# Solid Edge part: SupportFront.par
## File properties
Author: wojci
Template: ISO Metric Part.par
Last saved by: wojci
Revision: 29
Application: Solid Edge
Username: wojci
Accuracy: 0.990
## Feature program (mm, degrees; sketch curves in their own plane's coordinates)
sketch for "unnamed Protrusion 1" plane through (0, 0, 0) normal (0, -1, 0) x-axis (1, 0, 0)
  line (8, 17) -> (29.5448, 47.6494)
  line (3, 0) -> (8, 17)
  line (0, 0) -> (3, 0)
  line (0, 0) -> (0, 54.25)
  line (0, 54.25) -> (3, 54.25)
  line (3, 54.25) -> (15.254, 54.25)
extrude "unnamed Protrusion 1" add finite 20 along -normal
fillet "Round_2" radius 20
sketch for "ExtrudedCutout_8" plane through (14, 20, 28.625) normal (0, 1, 0) x-axis (-1, 0, 0)
extrude "ExtrudedCutout_8" cut finite 10 along -normal
sketch for "unnamed Cutout 1" plane through (9.0718, 10, 57.6326) normal (0, 0, 1) x-axis (-1, 0, 0)
  line (-21.9282, -10) -> (5.0718, -10)
extrude "unnamed Cutout 1" cut through along -normal
sketch for "Hole_1" plane through (13.5, 0, 28.5) normal (0, -1, 0) x-axis (0.575078, 0, 0.818099)
  hole centre (24.8931, 5.8862) bore radius 1.5
hole "Hole_1" diameter 3 finite
sketch for "ExtrudedProtrusion_2" #1 plane through (0, 5, 27) normal (-1, 0, 0) x-axis (0, 0, -1)
  line (-27.25, -7.25) -> (-17.5, -7.25)
  line (-17.5, -7.25) -> (-17.5, -12.75)
  line (-17.5, -12.75) -> (-27.25, -12.75)
  line (-27.25, -12.75) -> (-27.25, -7.25)
sketch for "ExtrudedProtrusion_2" #2 plane through (0, 5, 27) normal (-1, 0, 0) x-axis (0, 0, -1)
  line (10.25, -7.25) -> (10.25, -12.75)
  line (10.25, -12.75) -> (24.75, -12.75)
  line (24.75, -12.75) -> (24.75, -7.25)
  line (24.75, -7.25) -> (10.25, -7.25)
extrude "ExtrudedProtrusion_2" add finite 1.25 along +normal
sketch for "Hole_2" plane through (-1.25, 5, 49.125) normal (-1, 0, 0) x-axis (0, -1, 0)
  hole centre (-10, 0.125) bore radius 1.2295
hole "Hole_2" nominal diameter 3 through  ThreadDepth = 6.2 mm
sketch for "unnamed Hole 1" plane through (-1.25, 5, 49.125) normal (-1, 0, 0) x-axis (0, -1, 0)
  hole centre (-10, -36.125) bore radius 1.2295
hole "unnamed Hole 1" through
sketch for "unnamed Hole 2" plane through (-1.25, 5, 49.125) normal (-1, 0, 0) x-axis (0, -1, 0)
  hole centre (-10, -43.125) bore radius 1.2295
hole "unnamed Hole 2" through
pattern "unnamed Pattern 1" of "Hole_2", "unnamed Hole 1", "unnamed Hole 2"
sketch for "unnamed Cutout 2" #1 plane through (2.75, 5, 49.125) normal (-1, 0, 0) x-axis (0, -1, 0)
  circle centre (-10, -36.125) radius 3.25
sketch for "unnamed Cutout 2" #2 plane through (2.75, 5, 49.125) normal (-1, 0, 0) x-axis (0, -1, 0)
  circle centre (-10, -43.125) radius 3.25
extrude "unnamed Cutout 2" cut through along -normal
sketch for "unnamed Cutout 3" plane through (2.75, 5, 49.125) normal (-1, 0, 0) x-axis (0, -1, 0)
  circle centre (-10, 0.125) radius 3.25
extrude "unnamed Cutout 3" cut through along -normal
sketch for "unnamed Cutout 4" plane through (0, 10, 54.25) normal (-0.965107, -0.2586, 0.04117) x-axis (0, -0.157224, -0.987563)
  line (1.5722, 10.2327) -> (0, 0)
  line (0, 0) -> (50.8828, 0)
  line (50.8828, 0) -> (51.199, 2.058)
  line (51.199, 2.058) -> (1.5722, 10.2327)
extrude "unnamed Cutout 4" cut through along +normal
sketch for "unnamed Cutout 5" plane through (1.5, 10, 0) normal (0, 0, -1) x-axis (0, -1, 0)
  line (10, 1.5) -> (8, 1.5)
  line (8, 1.5) -> (10, 0.9641)
  line (10, 0.9641) -> (10, 1.5)
extrude "unnamed Cutout 5" cut through along -normal
sketch for "ExtrudedCutout_13" plane through (14.2679, 0, 28.625) normal (0, -1, 0) x-axis (1, 0, 0)
  line (-14.345, -27.625) -> (-10.2843, -25.2805)
  line (-11.2679, -28.625) -> (-10.2843, -25.2805)
  line (-11.2679, -28.625) -> (-15.5179, -28.625)
  line (-15.5179, -28.625) -> (-15.5179, -27.625)
  line (-15.5179, -27.625) -> (-14.345, -27.625)
extrude "ExtrudedCutout_13" cut finite 10 along -normal
sketch used by "unnamed Cutout 6" plane through (15.5, 10, 43.2085) normal (0, 1, 0) x-axis (-1, 0, 0)
extrude "unnamed Cutout 6" cut through along +normal
fillet "Round_10" radius 7
sketch for "unnamed Protrusion 2" plane through (1.5, 15, 0) normal (0, 0, -1) x-axis (0, 1, 0)
extrude "unnamed Protrusion 2" add finite 6 along +normal
chamfer "Chamfer_2" setback 9.96
sketch for "ExtrudedProtrusion_5" plane through (7.002, 10, 54.25) normal (0, 0, 1) x-axis (1, 0, 0)
extrude "ExtrudedProtrusion_5" add finite 0.5 along +normal
sketch for "ExtrudedProtrusion_6" plane through (7.0753, 10, 54.75) normal (0, 0, 1) x-axis (1, 0, 0)
extrude "ExtrudedProtrusion_6" add finite 5 along +normal
chamfer "Chamfer_3" setback 4.98
chamfer "Chamfer_4" setback 3
chamfer "Chamfer_5" setback 5
chamfer "Chamfer_6" setback 5.498
fillet "Round_11" radius 12
fillet "Round_12" radius 3.5
logasc func "Lip_Groove_2"  LipOrGrooveWidth = 1.25 mm; LipOrGrooveHeight = 0.4 mm
logasc func "Lip_Groove_3"  LipOrGrooveWidth = 1.25 mm; LipOrGrooveHeight = 0.4 mm
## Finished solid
Body 1: solid body, 52 faces, 132 edges, 79 vertices.
  Faces by surface: plane 39, cylinder 12, blend 1
  Edges by curve: line 96, circle 15, ellipse 12, intersection 9
Bounding box of the edges (mm; curved faces can reach further): 37.000 x 20.000 x 66.250, from (-6, 0, -6) to (31, 20, 60.25).
Cylindrical faces by radius (mm): R1.2295 x3, R1.5 x1, R3.25 x3, R3.5 x1, R8 x1, R12 x2, R20 x1
Planar faces by outward normal: +x 4, +y 4, +z 4, -x 4, -y 5, -z 4, oblique 14
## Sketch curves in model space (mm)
line (-1.25, 0, 1) -> (3.2941, 0, 1)
line (-1.25, 0, 0) -> (-1.25, 0, 1)
line (-1.25, 0, 1) -> (-0.0771, 0, 1)
line (-0.0771, 0, 1) -> (3.9837, 0, 3.3445)
line (3, 0, 0) -> (3.9837, 0, 3.3445)
line (3, 0, 0) -> (-1.25, 0, 0)
line (0, 2, 0) -> (0.5359, 0, 0)
line (0.5359, 0, 0) -> (0, 0, 0)
line (0, 0, 0) -> (0, 2, 0)
line (0, 10, 57.6326) -> (31, 10, 57.6326)
line (31, 20, 57.6326) -> (4, 20, 57.6326)
line (4, 20, 57.6326) -> (16, 10, 57.6326)
line (16, 10, 57.6326) -> (31, 10, 57.6326)
line (31, 10, 57.6326) -> (31, 20, 57.6326)
line (4, 20, 42.25) -> (8, 20, 42.25)
line (8, 20, 42.25) -> (15.254, 20, 54.25)
line (15.254, 20, 54.25) -> (3, 20, 54.25)
line (3, 20, 54.25) -> (4, 20, 42.25)
line (0, 2, 4) -> (0, 2, 0)
line (0, 10, 54.25) -> (0, 2, 4)
line (0, 10, 54.25) -> (2.6795, 0, 54.25)
line (0, 2, 4) -> (0.5389, -0.0112, 4)
line (0.5389, -0.0112, 4) -> (2.6795, 0, 54.25)
line (2.6795, 0, 54.25) -> (0, 10, 54.25)
line (0, 10, 54.25) -> (0, 2, 4)
circle centre (2.75, 15, 6) radius 3.25
circle centre (2.75, 15, 13) radius 3.25
circle centre (2.75, 15, 49.25) radius 3.25
circle centre (23, 10, 52.25) radius 12
line (0, 15, 54.25) -> (0, 15, 0)
line (0, 17.75, 2.25) -> (0, 12.25, 2.25)
line (0, 12.25, 2.25) -> (0, 12.25, 16.75)
line (0, 12.25, 16.75) -> (0, 17.75, 16.75)
line (0, 17.75, 16.75) -> (0, 17.75, 2.25)
line (0, 12.25, 44.5) -> (0, 17.75, 44.5)
line (0, 17.75, 44.5) -> (0, 17.75, 54.25)
line (0, 17.75, 54.25) -> (0, 12.25, 54.25)
line (0, 12.25, 54.25) -> (0, 12.25, 44.5)
line (0, 0, 17) -> (8, 0, 17)
line (0, 0, 0) -> (22, 0, 0)
line (0, 0, 42.25) -> (3, 0, 42.25)
line (0, 0, 49.25) -> (3, 0, 49.25)
line (0, 0, 52.25) -> (23, 0, 52.25)
line (3, 0, 54.25) -> (3, 0, 0)
line (0, 0, 54.25) -> (3, 0, 54.25)
line (3, 0, 54.25) -> (15.254, 0, 54.25)
arc centre (23, 0, 52.25) radius 8 from (15.254, 0, 54.25) through (26.5685, 0, 59.41) to (29.5448, 0, 47.6494)
line (8, 0, 17) -> (29.5448, 0, 47.6494)
line (3, 0, 0) -> (8, 0, 17)
line (0, 0, 0) -> (3, 0, 0)
line (0, 0, 0) -> (0, 0, 54.25)
line (4, 0, 52.25) -> (4, 0, 0)
line (8, 0, 52.25) -> (8, 0, 0)
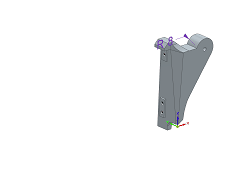
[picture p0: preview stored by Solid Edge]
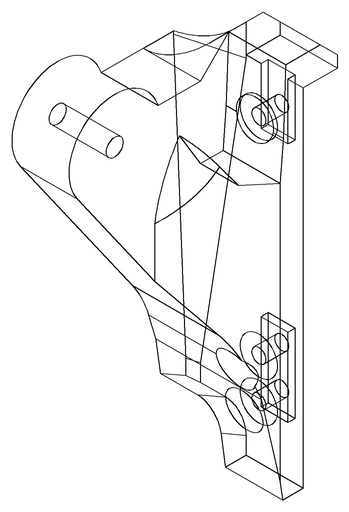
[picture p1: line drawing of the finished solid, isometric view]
